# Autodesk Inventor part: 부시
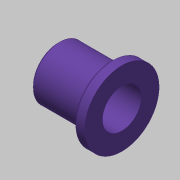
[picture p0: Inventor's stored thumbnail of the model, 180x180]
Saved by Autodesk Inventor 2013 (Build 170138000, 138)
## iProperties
Created: 2019-10
Part Number: 부시
Material: 강철, 연강
Document SubType Name: Modeling
Designer: mduedu
Density: 1 g/cm^3
Author: mduedu
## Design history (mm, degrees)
sketch "스케치1"
  geometry: L1 (0, 0)-(-18, 0); L2 (0, -5.5)-(0, -10.5); L3 (0, -10.5)-(-3, -10.5); L4 (-3, -10.5)-(-3, -7.5); L5 (-3, -7.5)-(-18, -7.5); L6 (-18, -7.5)-(-18, -5.5); L7 (-18, -5.5)-(0, -5.5)
  constraints: 14 end point, 3 parallel, 2 horizontal, 2 perpendicular, 2 vertical alignment
  dimensions: "d0" = 18 distance of L1.start L1.end; "d1" = 11 diameter of L7 L1; "d2" = 15 diameter of L5 L1; "d3" = 21 diameter of L3 L1; "d4" = 3 distance of L2.end L3.end
revolve "회전1" sketch "스케치1" stored, may be unused: angle "d5" = 90 deg
chamfer "모따기1" distance "d6" = 0.5; stored, may be unused: second distance "d7" = 2, angle "d8" = 45 deg
chamfer "모따기2" distance "d9" = 0.5; stored, may be unused: second distance "d10" = 2, angle "d11" = 45 deg
node "솔리드1"
